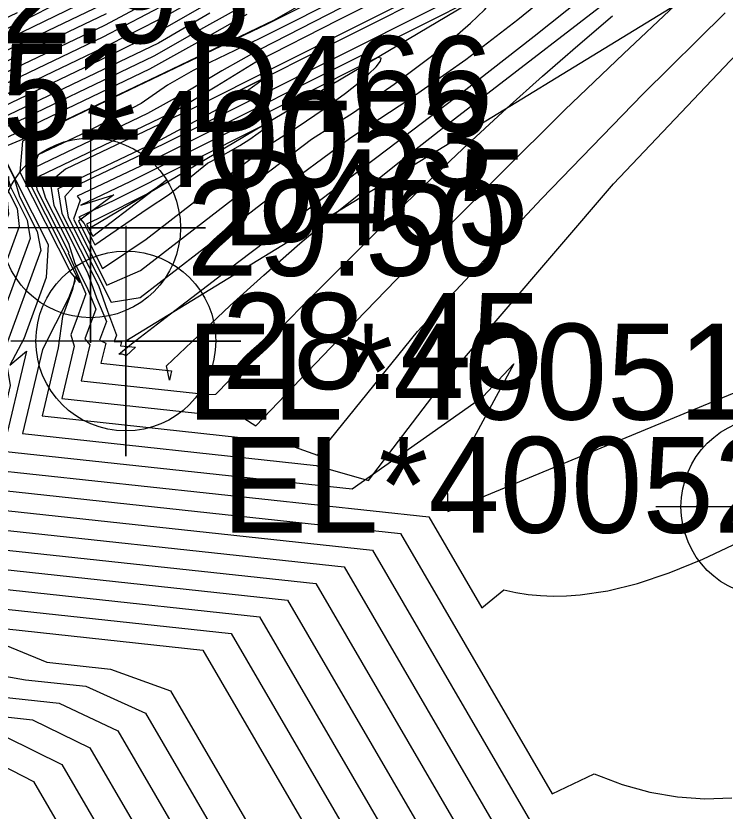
# Model space of a CAD drawing. Extents: x 2356077 to 2359823, y 225951 to 227822.
# Drawn here: x 2356639.42 to 2356657.91, y 226970.32 to 226991.05 of the extents above; entities that cross this region are included whole.
import ezdxf

# ---------------------------------------------------------------- set-up
doc = ezdxf.new("R2010")
doc.units = 0
for name, color, linetype in [('DTM Contours Major', 7, 'Continuous'), ('DTM Contours Minor', 7, 'Continuous'), ('Exist DTM Breakline', 7, 'Continuous'), ('Exist DTM Breakline Cogo Comment', 7, 'Continuous'), ('Exist DTM Breakline Cogo Elevation', 7, 'Continuous'), ('Exist DTM Breakline Cogo Number', 7, 'Continuous'), ('Exist DTM Breakline Cogo Point CELL', 7, 'Continuous'), ('Exist DTM Regular Point CELL', 7, 'Continuous'), ('PH Exist DTM Point', 7, 'Continuous')]:
    doc.layers.add(name, color=color, linetype=linetype)

msp = doc.modelspace()

# ---------------------------------------------------------------- linework, layer by layer
at = {"layer": 'DTM Contours Major'}
for points in [[(2356660.139, 226997.135), (2356647.814, 226990.943), (2356645.671, 226989.843), (2356644.658, 226989.214), (2356643.586, 226988.574), (2356640.011, 226986.865), (2356640.192, 226986.298), (2356640.787, 226985.127), (2356640.95, 226984.596), (2356641.272, 226983.962), (2356641.496, 226983.404), (2356641.213, 226982.633), (2356641.346, 226982.477), (2356641.122, 226981.534)], [(2356650.183, 226977.987), (2356651.566, 226975.612), (2356652.134, 226976.085), (2356652.448, 226976.018), (2356652.767, 226975.967), (2356653.092, 226975.934), (2356653.425, 226975.92), (2356653.769, 226975.925), (2356654.123, 226975.951), (2356654.847, 226976.062), (2356655.62, 226976.253), (2356656.446, 226976.526), (2356657.327, 226976.883), (2356658.263, 226977.326), (2356659.257, 226977.854), (2356659.882, 226978.213), (2356660.203, 226978.404), (2356661.989, 226979.563), (2356663.879, 226980.966), (2356665.824, 226982.623), (2356667.774, 226984.545), (2356669.68, 226986.743), (2356671.491, 226989.227), (2356673.506, 226992.595)], [(2356641.848, 226992.056), (2356639.505, 226990.872), (2356637.094, 226989.719), (2356636.929, 226989.45), (2356637.206, 226988.905), (2356637.228, 226988.651), (2356637.335, 226988.441), (2356637.235, 226988.048), (2356634.985, 226981.922), (2356634.704, 226980.793), (2356634.222, 226978.763), (2356634.309, 226978.722), (2356634.119, 226976.703), (2356633.725, 226975.05), (2356635.145, 226974.723), (2356636.693, 226974.556), (2356638.19, 226974.002), (2356639.666, 226973.741), (2356641.238, 226973.571), (2356642.799, 226972.865), (2356669.489, 226927.021)], [(2356643.381, 226991.381), (2356641.685, 226990.498), (2356638.035, 226988.753), (2356638.018, 226988.397), (2356638.209, 226988.021), (2356638.465, 226987.404), (2356638.478, 226987.282), (2356638.655, 226986.933), (2356638.656, 226986.501), (2356637.045, 226982.115), (2356636.858, 226981.373), (2356636.733, 226980.847), (2356636.875, 226980.422), (2356636.723, 226979.178), (2356636.471, 226978.118), (2356636, 226976.952), (2356646.501, 226975.817)], [(2356645.437, 226991.091), (2356644.152, 226990.361), (2356642.896, 226989.661), (2356638.996, 226987.796), (2356639.11, 226987.337), (2356639.374, 226986.817), (2356639.509, 226986.343), (2356639.975, 226985.426), (2356640.068, 226984.931), (2356639.098, 226982.291), (2356639.185, 226981.887), (2356639.27, 226981.409), (2356638.893, 226979.826), (2356638.561, 226979.243), (2356650.183, 226977.987)], [(2356641.122, 226981.534), (2356644.417, 226981.178), (2356644.63, 226981.186), (2356646.031, 226982.62), (2356647.371, 226983.976), (2356648.654, 226985.255), (2356649.885, 226986.459), (2356651.07, 226987.588), (2356652.215, 226988.645), (2356653.149, 226989.48), (2356654.064, 226990.278), (2356654.969, 226991.051)], [(2356642.408, 226986.731), (2356641.111, 226986.111), (2356641.971, 226986.386), (2356641.052, 226985.695), (2356641.678, 226984.462), (2356642.811, 226985.23), (2356644.936, 226986.868), (2356646.094, 226987.742), (2356646.773, 226988.169), (2356647.424, 226988.61), (2356648.01, 226989.039), (2356648.338, 226989.299), (2356648.609, 226989.531), (2356648.809, 226989.724), (2356648.924, 226989.868), (2356648.939, 226989.951), (2356648.839, 226989.962), (2356642.408, 226986.731)], [(2356646.501, 226975.817), (2356660.722, 226951.39), (2356664.408, 226949.18), (2356666.744, 226948.239), (2356669.072, 226947.782), (2356671.346, 226947.751), (2356673.516, 226948.089), (2356675.535, 226948.741), (2356677.354, 226949.648), (2356677.708, 226949.867), (2356678.051, 226950.096), (2356678.385, 226950.333), (2356678.708, 226950.58), (2356679.023, 226950.837), (2356679.33, 226951.104), (2356679.656, 226951.409), (2356679.975, 226951.726), (2356680.286, 226952.056), (2356680.59, 226952.4), (2356680.889, 226952.757)]]:
    msp.add_lwpolyline(points, dxfattribs=at)
at = {"layer": 'DTM Contours Minor'}
for points in [[(2356660.818, 226997.073), (2356644.084, 226988.665), (2356640.707, 226987.051), (2356640.31, 226986.725), (2356640.401, 226986.105), (2356641.286, 226984.362), (2356641.518, 226983.696), (2356641.775, 226983.082), (2356641.597, 226982.596), (2356641.759, 226982.519), (2356641.634, 226981.992)], [(2356656.111, 226994.565), (2356645.16, 226989.064), (2356645.962, 226989.462), (2356645.118, 226988.849), (2356643.181, 226987.814), (2356640.513, 226986.539), (2356640.618, 226985.896), (2356641.571, 226984.019), (2356641.802, 226983.354), (2356642.041, 226982.723), (2356641.982, 226982.563), (2356642.173, 226982.561), (2356642.146, 226982.451)], [(2356653.017, 226994.103), (2356645.776, 226990.465), (2356644.037, 226989.628), (2356643.369, 226989.24), (2356642.683, 226988.769), (2356641.264, 226988.031), (2356640.001, 226987.427), (2356639.741, 226986.75), (2356641.086, 226984.102), (2356640.964, 226984.258), (2356640.888, 226983.915), (2356640.631, 226983.214), (2356640.52, 226982.393), (2356640.098, 226980.618)], [(2356639.586, 226980.16), (2356647.245, 226979.331), (2356648.605, 226978.938), (2356650.54, 226981.463), (2356654.997, 226986.671), (2356661.888, 226993.947)], [(2356643.246, 226987.698), (2356640.909, 226986.581), (2356640.694, 226986.342), (2356640.776, 226985.802), (2356641.9, 226983.589), (2356642.652, 226983.708), (2356646.121, 226986.382), (2356648.146, 226987.879), (2356649.663, 226988.867), (2356651.142, 226989.912), (2356652.505, 226990.953), (2356653.288, 226991.596), (2356653.956, 226992.186), (2356654.477, 226992.699), (2356654.818, 226993.109), (2356654.946, 226993.39), (2356654.829, 226993.517), (2356643.246, 226987.698)], [(2356650.916, 226993.321), (2356645.971, 226990.836), (2356639.591, 226987.786), (2356639.515, 226986.976), (2356640.848, 226984.352), (2356640.941, 226984.239), (2356640.95, 226984.126), (2356640.791, 226983.694), (2356640.107, 226982.351), (2356639.586, 226980.16)], [(2356648.559, 226992.328), (2356646.151, 226990.938), (2356643.694, 226989.759), (2356640.143, 226988.061), (2356638.987, 226987.588), (2356640.256, 226985.09), (2356640.206, 226984.225), (2356639.619, 226982.626), (2356639.259, 226981.947), (2356639.694, 226982.309), (2356639.073, 226979.701)], [(2356641.634, 226981.992), (2356643.474, 226981.793), (2356643.418, 226981.553), (2356643.346, 226981.925), (2356644.164, 226982.709), (2356645.004, 226983.495), (2356645.884, 226984.293), (2356646.82, 226985.113), (2356647.829, 226985.964), (2356649.285, 226987.141), (2356650.848, 226988.367), (2356654.101, 226990.871), (2356655.693, 226992.104)], [(2356639.384, 226991.947), (2356636.324, 226990.484), (2356636.06, 226990.288), (2356636.233, 226989.949), (2356636.367, 226989.359), (2356636.05, 226989.018), (2356636.001, 226989.017), (2356633.325, 226981.733), (2356632.978, 226980.314), (2356632.161, 226976.878), (2356632.248, 226975.617), (2356631.689, 226973.268), (2356632.945, 226972.907), (2356634.364, 226972.753), (2356635.787, 226972.198), (2356637.042, 226971.971), (2356638.453, 226971.818), (2356639.876, 226971.09), (2356648.246, 226956.715), (2356652.572, 226949.744), (2356656.689, 226942.799), (2356660.293, 226936.331)], [(2356644.797, 226991.884), (2356643.304, 226991.033), (2356641.657, 226990.201), (2356638.226, 226988.561), (2356638.236, 226988.186), (2356638.44, 226987.785), (2356638.653, 226987.155), (2356638.919, 226986.632), (2356638.939, 226986.19), (2356637.458, 226982.156), (2356637.291, 226981.499), (2356637.244, 226981.125), (2356637.435, 226980.574), (2356637.164, 226979.338), (2356636.951, 226978.44), (2356636.513, 226977.41), (2356647.237, 226976.251)], [(2356642.146, 226982.451), (2356642.532, 226982.409), (2356642.291, 226982.188), (2356642.241, 226982.209), (2356642.184, 226982.226), (2356642.102, 226982.226), (2356642.431, 226982.5), (2356643.444, 226983.283), (2356645.231, 226984.645), (2356649.116, 226987.582), (2356651.068, 226989.073), (2356652.93, 226990.521), (2356654.628, 226991.884)], [(2356639.386, 226991.665), (2356636.52, 226990.295), (2356636.277, 226990.078), (2356636.475, 226989.69), (2356636.509, 226989.413), (2356636.313, 226988.893), (2356636.334, 226988.842), (2356633.739, 226981.779), (2356633.409, 226980.432), (2356632.69, 226977.411), (2356632.707, 226975.852), (2356632.198, 226973.713), (2356633.495, 226973.361), (2356634.947, 226973.204), (2356636.393, 226972.653), (2356637.699, 226972.413), (2356639.151, 226972.256), (2356640.61, 226971.529), (2356649.209, 226956.759), (2356653.655, 226949.536), (2356657.893, 226942.368), (2356661.61, 226935.726)], [(2356641.875, 226991.747), (2356639.563, 226990.616), (2356637.278, 226989.524), (2356637.147, 226989.239), (2356637.458, 226988.627), (2356637.477, 226988.379), (2356637.599, 226988.139), (2356637.518, 226987.734), (2356635.393, 226981.95), (2356635.132, 226980.895), (2356634.706, 226979.105), (2356634.864, 226978.913), (2356634.578, 226976.937), (2356634.233, 226975.49), (2356635.684, 226975.179), (2356637.232, 226975.011), (2356638.652, 226974.838), (2356640.219, 226974.195), (2356641.883, 226974.015), (2356643.445, 226973.455), (2356647.788, 226965.996), (2356651.798, 226959.83), (2356656.631, 226952.317), (2356661.712, 226943.71)], [(2356643.452, 226991.73), (2356641.722, 226990.799), (2356637.843, 226988.945), (2356637.8, 226988.607), (2356637.978, 226988.257), (2356638.273, 226987.654), (2356638.227, 226987.557), (2356638.391, 226987.234), (2356638.372, 226986.809), (2356636.631, 226982.071), (2356636.426, 226981.25), (2356636.265, 226980.575), (2356636.341, 226980.243), (2356636.288, 226979.044), (2356635.99, 226977.789), (2356635.488, 226976.494), (2356645.764, 226975.383)], [(2356642.827, 226987.214), (2356641.01, 226986.346), (2356641.091, 226986.249), (2356640.914, 226985.75), (2356641.789, 226984.026), (2356642.661, 226984.414), (2356645.458, 226986.571), (2356647.12, 226987.832), (2356648.215, 226988.535), (2356649.276, 226989.272), (2356650.247, 226990.002), (2356650.801, 226990.45), (2356651.27, 226990.858), (2356651.63, 226991.21), (2356651.86, 226991.486), (2356651.936, 226991.668), (2356651.834, 226991.74), (2356642.827, 226987.214)], [(2356639.411, 226991.393), (2356636.713, 226990.104), (2356636.495, 226989.869), (2356636.718, 226989.429), (2356636.742, 226989.172), (2356636.606, 226988.739), (2356636.644, 226988.602), (2356634.154, 226981.826), (2356633.84, 226980.551), (2356633.245, 226978.047), (2356633.173, 226976.117), (2356632.707, 226974.158), (2356634.045, 226973.815), (2356635.53, 226973.654), (2356636.999, 226973.106), (2356638.357, 226972.856), (2356639.848, 226972.695), (2356641.343, 226971.968), (2356650.172, 226956.804), (2356654.73, 226949.293), (2356659.091, 226941.897), (2356662.925, 226935.082)], [(2356641.847, 226991.425), (2356637.461, 226989.328), (2356637.365, 226989.028), (2356637.719, 226988.332), (2356637.728, 226988.103), (2356637.864, 226987.836), (2356637.799, 226987.417), (2356635.803, 226981.983), (2356635.562, 226981.01), (2356635.274, 226979.798), (2356635.497, 226979.146), (2356635.033, 226977.158), (2356634.464, 226975.578), (2356644.292, 226974.515)], [(2356644.635, 226991.504), (2356643.224, 226990.685), (2356641.633, 226989.907), (2356638.418, 226988.37), (2356638.454, 226987.974), (2356638.671, 226987.547), (2356638.825, 226987.034), (2356639.183, 226986.33), (2356639.222, 226985.877), (2356637.871, 226982.198), (2356637.729, 226981.642), (2356637.796, 226981.232), (2356637.834, 226980.458), (2356637.433, 226978.772), (2356637.025, 226977.869), (2356647.974, 226976.685)], [(2356645.674, 226991.505), (2356644.306, 226990.743), (2356643.011, 226989.999), (2356638.803, 226987.987), (2356638.891, 226987.55), (2356639.139, 226987.063), (2356639.272, 226986.59), (2356639.711, 226985.727), (2356639.786, 226985.247), (2356638.692, 226982.269), (2356638.704, 226981.846), (2356638.853, 226981.352), (2356638.404, 226979.462), (2356638.049, 226978.785), (2356649.447, 226977.553)], [(2356639.073, 226979.701), (2356648.187, 226978.716), (2356651.588, 226981.121), (2356652.401, 226981.979), (2356650.657, 226978.758), (2356650.68, 226978.129), (2356651.138, 226978.3), (2356651.648, 226978.536), (2356657.992, 226981.159), (2356658.782, 226981.481), (2356660.629, 226983.436), (2356662.388, 226985.398), (2356664.035, 226987.352), (2356665.55, 226989.291), (2356666.915, 226991.208)], [(2356647.897, 226991.258), (2356645.778, 226990.175), (2356644.782, 226989.619), (2356643.896, 226989.086), (2356642.843, 226988.502), (2356639.894, 226987.092), (2356639.965, 226986.527), (2356640.799, 226984.884), (2356640.783, 226984.876), (2356641.241, 226983.804), (2356641.016, 226983.181), (2356640.851, 226982.731), (2356640.933, 226982.435), (2356640.61, 226981.076)], [(2356640.61, 226981.076), (2356645.36, 226980.562), (2356645.674, 226980.361), (2356648.006, 226982.805), (2356650.119, 226984.982), (2356652.024, 226986.907), (2356653.731, 226988.597), (2356655.253, 226990.065), (2356656.6, 226991.326)], [(2356639.453, 226991.13), (2356636.904, 226989.912), (2356636.712, 226989.659), (2356636.961, 226989.168), (2356636.983, 226988.916), (2356637.072, 226988.74), (2356636.942, 226988.333), (2356634.569, 226981.873), (2356634.272, 226980.671), (2356633.746, 226978.458), (2356633.777, 226978.399), (2356633.644, 226976.404), (2356633.216, 226974.604), (2356634.595, 226974.269), (2356636.112, 226974.105), (2356637.601, 226973.557), (2356639.013, 226973.298), (2356640.545, 226973.133), (2356642.075, 226972.41), (2356651.129, 226956.859), (2356655.776, 226948.991), (2356660.261, 226941.358)], [(2356641.772, 226991.106), (2356637.652, 226989.136), (2356637.583, 226988.818), (2356637.989, 226988.017), (2356637.977, 226987.831), (2356638.128, 226987.535), (2356638.086, 226987.115), (2356636.217, 226982.028), (2356635.994, 226981.13), (2356635.807, 226980.342), (2356635.81, 226980.056), (2356635.877, 226979.009), (2356635.51, 226977.467), (2356634.976, 226976.036), (2356645.028, 226974.949)], [(2356644.472, 226991.124), (2356643.131, 226990.339), (2356638.61, 226988.178), (2356638.673, 226987.763), (2356638.904, 226987.307), (2356639.043, 226986.824), (2356639.447, 226986.029), (2356639.505, 226985.563), (2356638.283, 226982.236), (2356638.177, 226981.807), (2356638.349, 226981.322), (2356638.25, 226980.513), (2356637.917, 226979.112), (2356637.537, 226978.327), (2356648.71, 226977.119)], [(2356640.098, 226980.618), (2356646.302, 226979.947), (2356647.281, 226979.595), (2356649.882, 226982.822), (2356653.117, 226986.283), (2356655.764, 226989.013), (2356657.905, 226991.132)], [(2356641.989, 226986.248), (2356641.056, 226985.801), (2356641.192, 226985.638), (2356641.474, 226985.084), (2356642.84, 226986.017), (2356643.418, 226986.398), (2356644.41, 226987.213), (2356644.683, 226987.346), (2356644.969, 226987.502), (2356645.252, 226987.67), (2356645.513, 226987.838), (2356645.736, 226987.993), (2356645.851, 226988.08), (2356645.937, 226988.153), (2356645.986, 226988.204), (2356645.991, 226988.23), (2356645.946, 226988.225), (2356645.844, 226988.184), (2356641.989, 226986.248)], [(2356641.571, 226985.764), (2356641.261, 226985.616), (2356641.418, 226985.306), (2356643.332, 226986.77), (2356643.222, 226986.665), (2356643.075, 226986.556), (2356642.85, 226986.407), (2356641.571, 226985.764)], [(2356649.447, 226977.553), (2356653.397, 226970.767), (2356654.495, 226971.287), (2356655.223, 226971.006), (2356655.945, 226970.806), (2356656.662, 226970.684), (2356657.374, 226970.637), (2356658.083, 226970.662)], [(2356648.71, 226977.119), (2356655.228, 226965.923), (2356656.96, 226965.963), (2356658.105, 226965.497)], [(2356647.974, 226976.685), (2356657.059, 226961.079), (2356659.374, 226960.433), (2356660.943, 226959.795), (2356662.516, 226959.437), (2356664.081, 226959.335), (2356665.629, 226959.464), (2356667.146, 226959.797), (2356668.624, 226960.31), (2356669.296, 226960.604), (2356669.959, 226960.931), (2356670.615, 226961.291), (2356671.264, 226961.685), (2356671.91, 226962.112), (2356672.552, 226962.572), (2356674.277, 226963.97), (2356675.968, 226965.568), (2356677.599, 226967.325), (2356679.144, 226969.2), (2356680.574, 226971.152), (2356681.862, 226973.142)], [(2356647.237, 226976.251), (2356658.891, 226956.234), (2356661.996, 226954.951), (2356664.025, 226954.185), (2356666.057, 226953.815), (2356668.061, 226953.793), (2356670.005, 226954.073), (2356671.854, 226954.605), (2356673.578, 226955.344), (2356674.033, 226955.58), (2356674.475, 226955.829), (2356674.907, 226956.09), (2356675.328, 226956.363), (2356675.739, 226956.647), (2356676.14, 226956.943), (2356677.255, 226957.866), (2356678.301, 226958.873), (2356679.281, 226959.952), (2356680.202, 226961.093), (2356681.068, 226962.282)], [(2356645.764, 226975.383), (2356662.553, 226946.546), (2356666.352, 226943.721), (2356668.271, 226942.774), (2356670.157, 226942.187), (2356671.988, 226941.911), (2356673.743, 226941.897), (2356675.402, 226942.096), (2356676.944, 226942.46), (2356677.92, 226942.78), (2356678.83, 226943.16), (2356679.675, 226943.602), (2356680.455, 226944.113), (2356681.168, 226944.698)], [(2356645.028, 226974.949), (2356664.384, 226941.702), (2356668.031, 226937.951), (2356669.521, 226937.052), (2356670.982, 226936.394), (2356672.416, 226935.952), (2356673.823, 226935.7), (2356675.204, 226935.61), (2356676.56, 226935.657), (2356678.092, 226935.854), (2356679.568, 226936.207), (2356680.967, 226936.726)], [(2356644.292, 226974.515), (2356666.216, 226936.857), (2356669.72, 226931.925), (2356670.762, 226931.2), (2356671.793, 226930.59), (2356672.819, 226930.088), (2356673.843, 226929.687), (2356674.87, 226929.38), (2356675.905, 226929.159), (2356678.039, 226928.958), (2356680.163, 226929.092), (2356682.217, 226929.567)]]:
    msp.add_lwpolyline(points, dxfattribs=at)
at = {"layer": 'Exist DTM Breakline'}
for points in [[(2356732.647, 227097.121), (2356743.457, 227064.303), (2356707.447, 227028.908), (2356663.982, 226995.84), (2356642.282, 226982.572)], [(2356730.086, 227095.133), (2356740.594, 227064.572), (2356703.676, 227031.845), (2356663.207, 226998.49), (2356641.363, 226985.524)]]:
    msp.add_lwpolyline(points, dxfattribs=at)
at = {"layer": 'Exist DTM Breakline Cogo Point CELL'}
for points in [[(2356641.363, 226988.524), (2356641.363, 226982.524), (2356641.363, 226985.524), (2356644.363, 226985.524), (2356638.363, 226985.524)], [(2356642.282, 226985.572), (2356642.282, 226979.572), (2356642.282, 226982.572), (2356645.282, 226982.572), (2356639.282, 226982.572)]]:
    msp.add_lwpolyline(points, dxfattribs=at)
for centre in [(2356641.363, 226985.524), (2356642.282, 226982.572)]:
    msp.add_circle(centre, 2.344, dxfattribs=at)
at = {"layer": 'Exist DTM Regular Point CELL'}
msp.add_lwpolyline([(2356659.099, 226981.25), (2356659.099, 226975.25), (2356659.099, 226978.25), (2356662.099, 226978.25), (2356656.099, 226978.25)], dxfattribs=at)
msp.add_circle((2356659.099, 226978.25), 2.344, dxfattribs=at)
at = {"layer": 'PH Exist DTM Point'}
msp.add_line((2356650.579, 226978.22), (2356650.579, 226978.22), dxfattribs=at)

# ---------------------------------------------------------------- texts
at = {"layer": 'Exist DTM Breakline Cogo Comment'}
for s, p in [('EL*40051', (2356628.067, 226987.825)), ('EL*40053', (2356637.155, 226986.589)), ('EL*40051', (2356643.863, 226980.524)), ('EL*40052', (2356644.782, 226977.572))]:
    msp.add_text(s, height=2.5, dxfattribs=at).set_placement(p)
at = {"layer": 'Exist DTM Breakline Cogo Elevation'}
for s, p in [('22.95', (2356637.155, 226990.339)), ('29.50', (2356643.863, 226984.274)), ('28.45', (2356644.782, 226981.322))]:
    msp.add_text(s, height=2.5, dxfattribs=at).set_placement(p)
at = {"layer": 'Exist DTM Breakline Cogo Number'}
for s, p in [('D466', (2356643.863, 226988.024)), ('D465', (2356644.782, 226985.072))]:
    msp.add_text(s, height=2.5, dxfattribs=at).set_placement(p)

doc.saveas('drawing.dxf')
